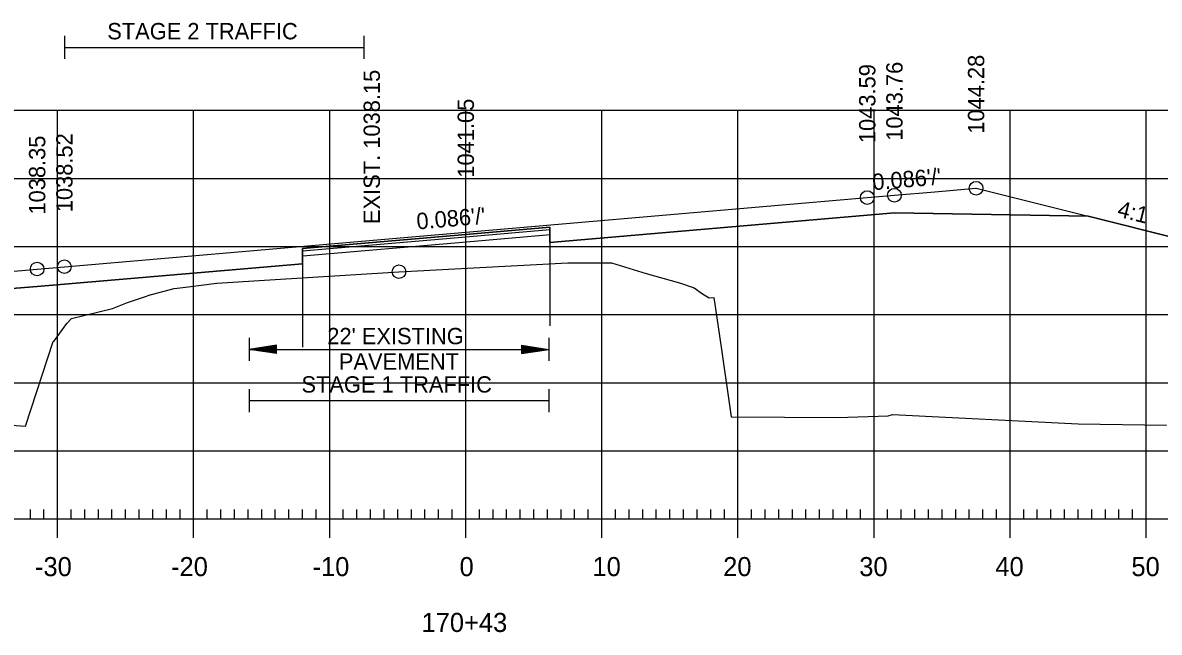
# Model space of a CAD drawing. Extents: x 1322838 to 1324533, y 339903 to 351025.
# Drawn here: x 1323671.2 to 1323754.7, y 347033.5 to 347078.3 of the extents above; entities that cross this region are included whole.
import ezdxf

# ---------------------------------------------------------------- set-up
doc = ezdxf.new("R2010")
doc.units = 0
for name, color, linetype in [('R_Alt Surface', 7, 'Continuous'), ('R_Axis', 7, 'Continuous'), ('R_Axis Annot', 7, 'Continuous'), ('R_Exist Surface', 7, 'Continuous'), ('R_Fin Surface', 7, 'Continuous'), ('R_Fin Surface Annot', 7, 'Continuous'), ('R_Grid', 7, 'Continuous'), ('R_No Plot', 7, 'Continuous'), ('R_Xsect Elev', 7, 'Continuous')]:
    doc.layers.add(name, color=color, linetype=linetype)

msp = doc.modelspace()

# ---------------------------------------------------------------- linework, layer by layer
at = {"layer": 'R_Alt Surface'}
msp.add_lwpolyline([(1323637.719, 347056.151), (1323672.215, 347058.893), (1323691.706, 347060.57), (1323691.716, 347061.695), (1323703.715, 347062.728), (1323709.887, 347063.258), (1323709.897, 347062.133), (1323735.215, 347064.311), (1323749.444, 347064.062)], dxfattribs=at)
at = {"layer": 'R_Axis'}
for p, q in [((1323673.715, 347040.439), (1323673.715, 347043.239)), ((1323683.715, 347040.439), (1323683.715, 347043.239)), ((1323693.715, 347040.439), (1323693.715, 347043.239)), ((1323703.715, 347040.439), (1323703.715, 347043.239)), ((1323713.715, 347040.439), (1323713.715, 347043.239)), ((1323723.715, 347040.439), (1323723.715, 347043.239)), ((1323733.715, 347040.439), (1323733.715, 347043.239)), ((1323743.715, 347040.439), (1323743.715, 347043.239)), ((1323753.715, 347040.439), (1323753.715, 347043.239)), ((1323563.715, 347041.839), (1323843.715, 347041.839)), ((1323671.715, 347041.839), (1323671.715, 347042.539)), ((1323672.715, 347041.839), (1323672.715, 347042.539)), ((1323674.715, 347041.839), (1323674.715, 347042.539)), ((1323675.715, 347041.839), (1323675.715, 347042.539)), ((1323676.715, 347041.839), (1323676.715, 347042.539)), ((1323677.715, 347041.839), (1323677.715, 347042.539)), ((1323678.715, 347041.839), (1323678.715, 347042.539)), ((1323679.715, 347041.839), (1323679.715, 347042.539)), ((1323680.715, 347041.839), (1323680.715, 347042.539)), ((1323681.715, 347041.839), (1323681.715, 347042.539)), ((1323682.715, 347041.839), (1323682.715, 347042.539)), ((1323684.715, 347041.839), (1323684.715, 347042.539)), ((1323685.715, 347041.839), (1323685.715, 347042.539)), ((1323686.715, 347041.839), (1323686.715, 347042.539)), ((1323687.715, 347041.839), (1323687.715, 347042.539)), ((1323688.715, 347041.839), (1323688.715, 347042.539)), ((1323689.715, 347041.839), (1323689.715, 347042.539)), ((1323690.715, 347041.839), (1323690.715, 347042.539)), ((1323691.715, 347041.839), (1323691.715, 347042.539)), ((1323692.715, 347041.839), (1323692.715, 347042.539)), ((1323694.715, 347041.839), (1323694.715, 347042.539)), ((1323695.715, 347041.839), (1323695.715, 347042.539)), ((1323696.715, 347041.839), (1323696.715, 347042.539)), ((1323697.715, 347041.839), (1323697.715, 347042.539)), ((1323698.715, 347041.839), (1323698.715, 347042.539)), ((1323699.715, 347041.839), (1323699.715, 347042.539)), ((1323700.715, 347041.839), (1323700.715, 347042.539)), ((1323701.715, 347041.839), (1323701.715, 347042.539)), ((1323702.715, 347041.839), (1323702.715, 347042.539)), ((1323704.715, 347041.839), (1323704.715, 347042.539)), ((1323705.715, 347041.839), (1323705.715, 347042.539)), ((1323706.715, 347041.839), (1323706.715, 347042.539)), ((1323707.715, 347041.839), (1323707.715, 347042.539)), ((1323708.715, 347041.839), (1323708.715, 347042.539)), ((1323709.715, 347041.839), (1323709.715, 347042.539)), ((1323710.715, 347041.839), (1323710.715, 347042.539)), ((1323711.715, 347041.839), (1323711.715, 347042.539)), ((1323712.715, 347041.839), (1323712.715, 347042.539)), ((1323714.715, 347041.839), (1323714.715, 347042.539)), ((1323715.715, 347041.839), (1323715.715, 347042.539)), ((1323716.715, 347041.839), (1323716.715, 347042.539)), ((1323717.715, 347041.839), (1323717.715, 347042.539)), ((1323718.715, 347041.839), (1323718.715, 347042.539)), ((1323719.715, 347041.839), (1323719.715, 347042.539)), ((1323720.715, 347041.839), (1323720.715, 347042.539)), ((1323721.715, 347041.839), (1323721.715, 347042.539)), ((1323722.715, 347041.839), (1323722.715, 347042.539)), ((1323724.715, 347041.839), (1323724.715, 347042.539)), ((1323725.715, 347041.839), (1323725.715, 347042.539)), ((1323726.715, 347041.839), (1323726.715, 347042.539)), ((1323727.715, 347041.839), (1323727.715, 347042.539)), ((1323728.715, 347041.839), (1323728.715, 347042.539)), ((1323729.715, 347041.839), (1323729.715, 347042.539)), ((1323730.715, 347041.839), (1323730.715, 347042.539)), ((1323731.715, 347041.839), (1323731.715, 347042.539)), ((1323732.715, 347041.839), (1323732.715, 347042.539)), ((1323734.715, 347041.839), (1323734.715, 347042.539)), ((1323735.715, 347041.839), (1323735.715, 347042.539)), ((1323736.715, 347041.839), (1323736.715, 347042.539)), ((1323737.715, 347041.839), (1323737.715, 347042.539)), ((1323738.715, 347041.839), (1323738.715, 347042.539)), ((1323739.715, 347041.839), (1323739.715, 347042.539)), ((1323740.715, 347041.839), (1323740.715, 347042.539)), ((1323741.715, 347041.839), (1323741.715, 347042.539)), ((1323742.715, 347041.839), (1323742.715, 347042.539)), ((1323744.715, 347041.839), (1323744.715, 347042.539)), ((1323745.715, 347041.839), (1323745.715, 347042.539)), ((1323746.715, 347041.839), (1323746.715, 347042.539)), ((1323747.715, 347041.839), (1323747.715, 347042.539)), ((1323748.715, 347041.839), (1323748.715, 347042.539)), ((1323749.715, 347041.839), (1323749.715, 347042.539)), ((1323750.715, 347041.839), (1323750.715, 347042.539)), ((1323751.715, 347041.839), (1323751.715, 347042.539)), ((1323752.715, 347041.839), (1323752.715, 347042.539))]:
    msp.add_line(p, q, dxfattribs=at)
at = {"layer": 'R_Axis Annot'}
for p, q in [((1323674.215, 347077.313), (1323674.215, 347075.608)), ((1323696.215, 347077.313), (1323696.215, 347075.608)), ((1323674.215, 347076.46), (1323696.215, 347076.46)), ((1323687.806, 347055.142), (1323687.806, 347053.436)), ((1323709.806, 347055.142), (1323709.806, 347053.436)), ((1323689.806, 347054.589), (1323687.806, 347054.289)), ((1323689.806, 347053.989), (1323687.806, 347054.289)), ((1323687.806, 347054.289), (1323709.806, 347054.289)), ((1323689.806, 347054.539), (1323688.14, 347054.289)), ((1323689.806, 347054.039), (1323688.14, 347054.289)), ((1323689.806, 347054.488), (1323688.484, 347054.289)), ((1323689.806, 347054.09), (1323688.484, 347054.289)), ((1323689.806, 347054.438), (1323688.817, 347054.289)), ((1323689.806, 347054.14), (1323688.817, 347054.289)), ((1323689.806, 347054.387), (1323689.156, 347054.289)), ((1323689.806, 347054.192), (1323689.156, 347054.289)), ((1323689.806, 347054.336), (1323689.49, 347054.289)), ((1323689.806, 347054.242), (1323689.49, 347054.289)), ((1323689.806, 347053.989), (1323689.806, 347054.589)), ((1323707.806, 347054.589), (1323709.806, 347054.289)), ((1323707.806, 347054.589), (1323707.806, 347053.989)), ((1323707.806, 347054.539), (1323709.472, 347054.289)), ((1323707.806, 347054.488), (1323709.128, 347054.289)), ((1323707.806, 347054.438), (1323708.795, 347054.289)), ((1323707.806, 347054.386), (1323708.456, 347054.289)), ((1323707.806, 347054.336), (1323708.122, 347054.289)), ((1323707.806, 347053.989), (1323709.806, 347054.289)), ((1323707.806, 347054.191), (1323708.456, 347054.289)), ((1323707.806, 347054.09), (1323709.128, 347054.289)), ((1323707.806, 347054.039), (1323709.472, 347054.289)), ((1323707.806, 347054.14), (1323708.795, 347054.289)), ((1323707.806, 347054.242), (1323708.122, 347054.289)), ((1323687.806, 347051.377), (1323687.806, 347049.671)), ((1323709.806, 347051.377), (1323709.806, 347049.671)), ((1323687.806, 347050.524), (1323709.806, 347050.524))]:
    msp.add_line(p, q, dxfattribs=at)
at = {"layer": 'R_Exist Surface'}
msp.add_lwpolyline([(1323665.255, 347049.084), (1323671.352, 347048.638), (1323673.385, 347054.865), (1323673.48, 347054.938), (1323674.385, 347056.176), (1323674.745, 347056.549), (1323677.75, 347057.296), (1323678.851, 347057.739), (1323680.02, 347058.119), (1323680.589, 347058.307), (1323680.629, 347058.32), (1323682.282, 347058.758), (1323682.913, 347058.838), (1323685.418, 347059.153), (1323688.919, 347059.378), (1323698.806, 347059.989), (1323704.271, 347060.285), (1323711.209, 347060.643), (1323713.262, 347060.638), (1323714.411, 347060.636), (1323716.979, 347059.858), (1323719.428, 347059.17), (1323720.499, 347058.798), (1323721.119, 347058.377), (1323721.61, 347058.07), (1323721.948, 347058.094), (1323722.489, 347054.457), (1323723.206, 347049.332), (1323731.048, 347049.288), (1323734.756, 347049.4), (1323735.073, 347049.503), (1323748.716, 347048.823), (1323755.201, 347048.72)], dxfattribs=at)
at = {"layer": 'R_Fin Surface'}
msp.add_lwpolyline([(1323666.795, 347059.718), (1323672.215, 347060.185), (1323674.215, 347060.357), (1323703.712, 347062.893), (1323703.715, 347062.894), (1323703.718, 347062.894), (1323733.216, 347065.431), (1323735.215, 347065.603), (1323738.189, 347065.858), (1323741.207, 347066.118), (1323741.215, 347066.119), (1323741.227, 347066.116), (1323745.325, 347065.091), (1323749.444, 347064.062), (1323749.446, 347064.061), (1323763.215, 347060.619)], dxfattribs=at)
at = {"layer": 'R_Grid'}
for p, q in [((1323563.715, 347071.839), (1323843.715, 347071.839)), ((1323673.715, 347041.839), (1323673.715, 347071.839)), ((1323683.715, 347041.839), (1323683.715, 347071.839)), ((1323693.715, 347041.839), (1323693.715, 347071.839)), ((1323703.715, 347041.839), (1323703.715, 347071.839)), ((1323713.715, 347041.839), (1323713.715, 347071.839)), ((1323723.715, 347041.839), (1323723.715, 347071.839)), ((1323733.715, 347041.839), (1323733.715, 347071.839)), ((1323743.715, 347041.839), (1323743.715, 347071.839)), ((1323753.715, 347041.839), (1323753.715, 347071.839)), ((1323563.715, 347066.839), (1323843.715, 347066.839)), ((1323563.715, 347061.839), (1323843.715, 347061.839)), ((1323563.715, 347056.839), (1323843.715, 347056.839)), ((1323563.715, 347051.839), (1323843.715, 347051.839)), ((1323563.715, 347046.839), (1323843.715, 347046.839)), ((1323563.715, 347041.839), (1323843.715, 347041.839))]:
    msp.add_line(p, q, dxfattribs=at)
at = {"layer": 'R_No Plot'}
for p, q in [((1323703.761, 347062.188), (1323709.921, 347062.717)), ((1323691.746, 347061.154), (1323703.761, 347062.188)), ((1323709.897, 347062.133), (1323709.897, 347056.024)), ((1323691.706, 347060.57), (1323691.706, 347054.461))]:
    msp.add_line(p, q, dxfattribs=at)
for points in [[(1323763.215, 347060.619), (1323749.446, 347064.061), (1323749.444, 347064.062), (1323735.215, 347064.311), (1323709.897, 347062.133), (1323709.887, 347063.258), (1323703.715, 347062.728), (1323691.716, 347061.695), (1323691.706, 347060.57), (1323672.215, 347058.893), (1323637.719, 347056.151)], [(1323691.714, 347061.527), (1323703.729, 347062.562), (1323709.889, 347063.091)], [(1323665.255, 347049.084), (1323671.352, 347048.638), (1323673.385, 347054.865), (1323673.48, 347054.938), (1323674.385, 347056.176), (1323674.745, 347056.549), (1323677.75, 347057.296), (1323678.851, 347057.739), (1323680.02, 347058.119), (1323680.589, 347058.307), (1323680.629, 347058.32), (1323682.282, 347058.758), (1323682.913, 347058.838), (1323685.418, 347059.153), (1323688.919, 347059.378), (1323698.806, 347059.989), (1323704.271, 347060.285), (1323711.209, 347060.643), (1323713.262, 347060.638), (1323714.411, 347060.636), (1323716.979, 347059.858), (1323719.428, 347059.17), (1323720.499, 347058.798), (1323721.119, 347058.377), (1323721.61, 347058.07), (1323721.948, 347058.094), (1323722.489, 347054.457), (1323723.206, 347049.332), (1323731.048, 347049.288), (1323734.756, 347049.4), (1323735.073, 347049.503), (1323748.716, 347048.823), (1323755.201, 347048.72)]]:
    msp.add_lwpolyline(points, dxfattribs=at)
for centre in [(1323735.215, 347065.603), (1323741.215, 347066.119), (1323733.216, 347065.431), (1323672.215, 347060.185), (1323674.215, 347060.357), (1323698.806, 347059.989)]:
    msp.add_circle(centre, 0.5, dxfattribs=at)

# ---------------------------------------------------------------- texts
at = {"layer": 'R_Axis Annot'}
for s, height, p in [('STAGE 2 TRAFFIC', 1.2, (1323677.368, 347077.051)), ("22' EXISTING ", 1.2, (1323693.538, 347054.664)), ('PAVEMENT', 1.2, (1323694.389, 347052.798)), ('STAGE 1 TRAFFIC', 1.2, (1323691.639, 347051.115)), ('-30', 1.4, (1323672.056, 347037.639)), ('-20', 1.4, (1323682.056, 347037.639)), ('-10', 1.4, (1323692.453, 347037.639)), ('0', 1.4, (1323703.258, 347037.639)), ('10', 1.4, (1323713.026, 347037.639)), ('20', 1.4, (1323722.63, 347037.639)), ('30', 1.4, (1323732.63, 347037.639)), ('40', 1.4, (1323742.63, 347037.639)), ('50', 1.4, (1323752.63, 347037.639)), ('170+43', 1.4, (1323700.463, 347033.539))]:
    msp.add_text(s, height=height, dxfattribs=at).set_placement(p)
at = {"layer": 'R_Fin Surface Annot'}
for s, rotation, p in [('1043.59', 90, (1323733.816, 347069.431)), ('1043.76', 90, (1323735.815, 347069.603)), ('1044.28', 90, (1323741.815, 347070.119)), ('1041.05', 90, (1323704.315, 347066.894)), ('1038.35', 90, (1323672.815, 347064.185)), ('1038.52', 90, (1323674.815, 347064.357)), ("0.086'/'", 4.91586, (1323733.642, 347065.969)), ("0.086'/'", 4.91531, (1323700.142, 347063.088)), ('4:1', 345.96379, (1323751.53, 347064.055))]:
    msp.add_text(s, height=1.2, rotation=rotation, dxfattribs=at).set_placement(p)
at = {"layer": 'R_Xsect Elev'}
msp.add_text('EXIST. 1038.15', height=1.2, rotation=90, dxfattribs=at).set_placement((1323697.406, 347063.489))

doc.saveas('drawing.dxf')
